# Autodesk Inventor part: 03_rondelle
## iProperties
Shininess: 20.0
Length Units: 11270
Angle Units: 11279
Time Units: 11290
Mass Units: 11283
Length Display Precision: 3
Angle Display Precision: 2
Created: 2000-10
Part Number: 03_rondelle
Material: Par défaut
Document SubType Name: Modélisation
Density: 0.0
Volumn: 0.0
Area: 0.0
PropertySet Name: Model Information
Control State: 0
Master: False
Checked Out: False
Author: Laurent GAUTHERON
